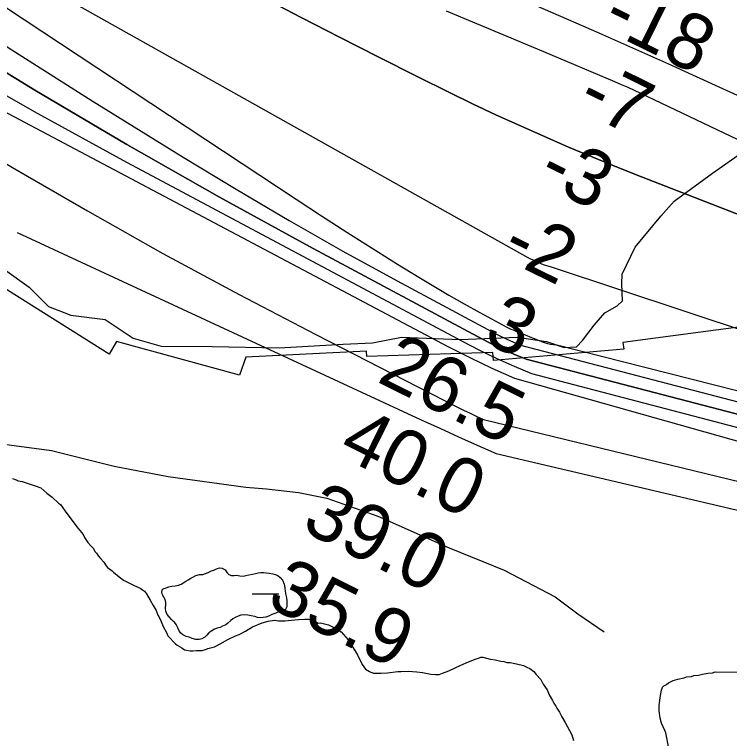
# Model space of a CAD drawing. Extents: x 3263578 to 3301413, y 764927 to 798602.
# Drawn here: x 3281091 to 3281950, y 782337 to 783206 of the extents above; entities that cross this region are included whole.
import ezdxf

# ---------------------------------------------------------------- set-up
doc = ezdxf.new("R2010")
doc.units = 0
for name, color, linetype in [('V-RIVR-EDGE', 7, 'Continuous'), ('V-RIVR-RANG', 7, 'Continuous'), ('V-ROAD-CNTR', 7, 'Continuous'), ('V-RRAP-RVMT', 7, 'Continuous'), ('V-SITE-VEGE', 7, 'Continuous'), ('V-TOPO-DPTH', 7, 'Continuous'), ('V-TOPO-MAJR', 7, 'Continuous'), ('V-TOPO-MINR', 7, 'Continuous'), ('V-TOPO-WATR', 7, 'Continuous'), ('V-WETL-SWMP', 7, 'Continuous')]:
    doc.layers.add(name, color=color, linetype=linetype)

msp = doc.modelspace()

# ---------------------------------------------------------------- linework, layer by layer
at = {"layer": 'V-RIVR-EDGE'}
msp.add_lwpolyline([(3281079.06, 782899.95), (3281109, 782879.01), (3281131.98, 782855.91), (3281158.9, 782845.42), (3281200.18, 782840.1), (3281233.6, 782817.85), (3281267.48, 782808.2), (3281328.77, 782807.61), (3281409.18, 782806.11), (3281485.7, 782810.7), (3281520.91, 782811.92), (3281556.13, 782818.79), (3281626.55, 782816.01), (3281694.8, 782818.88), (3281729.99, 782813.58), (3281751.28, 782806.57), (3281766.06, 782807.4), (3281773.46, 782814.77), (3281787.42, 782833.43), (3281800.06, 782848.18), (3281814.86, 782856.4), (3281821.4, 782862.47), (3281820.58, 782882.9), (3281821.04, 782894.64), (3281836.33, 782926.76), (3281867.29, 782964.07), (3281883.42, 782982.29), (3281929.58, 783015.64), (3281968.33, 783042.93)], dxfattribs=at)
at = {"layer": 'V-ROAD-CNTR'}
msp.add_lwpolyline([(3281078.63, 782690.69), (3281135.53, 782682.77), (3281210.98, 782663.94), (3281275.74, 782651.68), (3281369.17, 782638.83), (3281393.93, 782636.94), (3281432.33, 782632.66), (3281466.46, 782625.58), (3281527.71, 782604.09), (3281613, 782566.06), (3281679.07, 782539.44), (3281740.33, 782507.16), (3281767.85, 782486.68), (3281799.25, 782465.3)], dxfattribs=at)
at = {"layer": 'V-RRAP-RVMT'}
for points in [[(3281665.46, 782800.61), (3281514.13, 782795.79), (3281513.96, 782802.27), (3281368.97, 782794.99), (3281361.31, 782773.49), (3281213.67, 782813.79), (3281204.98, 782798.56), (3281071.75, 782882.28), (3281075.21, 782886.74), (3280952.92, 782963.69), (3280949.52, 782959.02), (3280830.38, 783051.85), (3280817.92, 783039.11), (3280717.22, 783151.35), (3280705.68, 783144.47), (3280621.14, 783274.26)], [(3281972.58, 782832.43), (3281821.58, 782812.34), (3281822.75, 782804.38), (3281666.34, 782791.05), (3281665.46, 782800.61)]]:
    msp.add_lwpolyline(points, dxfattribs=at)
at = {"layer": 'V-SITE-VEGE'}
for points in [[(3281088.65, 782649.38), (3281093.33, 782647.54), (3281095.67, 782646.33), (3281100.37, 782645.67), (3281117.36, 782640.12), (3281122.64, 782638.27), (3281130.19, 782631.68), (3281136.6, 782626.88), (3281144.15, 782619.7)], [(3281144.15, 782619.7), (3281146.48, 782617.9), (3281152.25, 782610.16), (3281156.28, 782604.21), (3281167.84, 782589.32), (3281173.62, 782582.17), (3281175.34, 782578.61), (3281179.37, 782572.66), (3281182.84, 782568.49), (3281185.74, 782565.5), (3281188.04, 782561.34), (3281189.77, 782559.55), (3281192.08, 782555.98), (3281194.98, 782553), (3281198.45, 782548.82), (3281201.33, 782544.66), (3281203.06, 782542.28), (3281208.31, 782538.67), (3281210.05, 782536.88), (3281217.04, 782531.47), (3281222.27, 782527.27), (3281233.96, 782521.21), (3281238.64, 782519.38), (3281242.15, 782517.56), (3281245.07, 782515.75), (3281247.4, 782513.95), (3281249.71, 782510.97), (3281254.3, 782503.24), (3281257.74, 782496.72), (3281261.18, 782490.78), (3281263.46, 782485.45), (3281264.61, 782483.66), (3281267.47, 782477.73), (3281269.73, 782471.81), (3281274.32, 782463.5), (3281275.46, 782460.54), (3281284.74, 782450.98), (3281286.48, 782449.19), (3281292.32, 782446.16), (3281295.23, 782443.76), (3281297.58, 782443.13), (3281302.27, 782442.47), (3281305.22, 782442.43), (3281309.94, 782442.95), (3281316.41, 782442.85), (3281320.55, 782443.97), (3281323.51, 782445.1)], [(3281323.51, 782445.1), (3281331.2, 782447.34), (3281338.32, 782450.77), (3281347.23, 782455.94), (3281356.72, 782460.51), (3281360.86, 782462.21), (3281368.58, 782466.22), (3281376.9, 782471.4), (3281388.74, 782475.94), (3281395.84, 782478.18), (3281403.51, 782479.25), (3281408.21, 782478.59), (3281415.87, 782478.47), (3281420, 782479.01), (3281427.66, 782479.48), (3281432.38, 782480), (3281440.04, 782480.47), (3281444.74, 782480.4), (3281450.03, 782479.15), (3281455.86, 782475.53), (3281458.81, 782476.07), (3281468.2, 782473.58), (3281476.97, 782469.33), (3281483.38, 782465.11), (3281492.08, 782455.56), (3281497.82, 782446.06), (3281503, 782437.73), (3281508.71, 782425.87), (3281512.75, 782420.51), (3281517.42, 782417.5), (3281522.1, 782415.66), (3281531.52, 782415.52), (3281539.19, 782416), (3281551.57, 782417.58), (3281555.7, 782417.52), (3281563.95, 782417.99), (3281574.53, 782417.24), (3281581, 782416.56), (3281590.98, 782414.64), (3281596.86, 782413.97), (3281600.98, 782413.91), (3281605.13, 782415.61), (3281612.83, 782418.44), (3281627.06, 782425.3), (3281636.54, 782429.28), (3281645.42, 782432.68), (3281648.38, 782433.81), (3281651.34, 782434.95), (3281653.7, 782434.91), (3281662.5, 782432.43), (3281668.37, 782431.75), (3281675.41, 782429.88), (3281678.94, 782429.83), (3281682.46, 782428.6), (3281686.58, 782428.54), (3281694.21, 782426.66), (3281702.42, 782424.77), (3281706.52, 782422.94), (3281710.02, 782421.12), (3281714.68, 782417.52), (3281717.57, 782413.95), (3281723.37, 782407.97), (3281726.24, 782402.63), (3281730.84, 782395.5), (3281733.11, 782389.58), (3281737.14, 782383.04), (3281738.85, 782379.48), (3281741.15, 782375.91), (3281742.29, 782373.54), (3281745.75, 782368.78), (3281748.62, 782363.44), (3281752.64, 782356.31), (3281760.66, 782341.47), (3281762.33, 782334.97)], [(3281877.02, 782325.61), (3281873.17, 782343.93), (3281872.03, 782346.89), (3281868.04, 782355.78), (3281866.36, 782361.69), (3281865.31, 782370.54), (3281865.4, 782376.43), (3281866.73, 782386.42), (3281868.04, 782395.23), (3281869.27, 782398.75), (3281871.06, 782400.49), (3281874.03, 782402.21), (3281876.41, 782403.94), (3281882.34, 782406.8), (3281887.67, 782408.48), (3281895.35, 782410.14), (3281898.31, 782411.27), (3281904.2, 782411.77), (3281907.16, 782412.91), (3281912.47, 782413.42), (3281917.2, 782414.52), (3281923.69, 782415.6), (3281929.59, 782416.11), (3281932.55, 782417.24), (3281959.04, 782416.85)]]:
    msp.add_lwpolyline(points, dxfattribs=at)
at = {"layer": 'V-TOPO-DPTH'}
for points in [[(3280689.61, 783473.12), (3281429.64, 782984.43), (3281459.85, 782964.67), (3281490.16, 782945.09), (3281520.65, 782925.78), (3281551.24, 782906.64), (3281576.56, 782890.95), (3281594.68, 782879.96), (3281612.93, 782869.19), (3281631.38, 782858.76), (3281649.96, 782848.57), (3281682.58, 782831.05), (3281684.97, 782829.82), (3281687.38, 782828.65), (3281689.83, 782827.55), (3281692.31, 782826.51), (3281724.05, 782813.8), (3281727.59, 782812.54), (3281731.17, 782811.47), (3281734.83, 782810.68), (3281738.53, 782810.07), (3281742.28, 782809.73), (3282707.96, 782564.89)], [(3280689.61, 783473.12), (3281429.64, 782984.43), (3281459.85, 782964.67), (3281490.16, 782945.09), (3281520.65, 782925.78), (3281551.24, 782906.64), (3281576.56, 782890.95), (3281594.68, 782879.96), (3281612.93, 782869.19), (3281631.38, 782858.76), (3281649.96, 782848.57), (3281682.58, 782831.05), (3281684.97, 782829.82), (3281687.38, 782828.65), (3281689.83, 782827.55), (3281692.31, 782826.51), (3281724.05, 782813.8), (3281727.59, 782812.54), (3281731.17, 782811.47), (3281734.83, 782810.68), (3281738.53, 782810.07), (3281742.28, 782809.73), (3282707.96, 782564.89)], [(3283888.62, 781898.87), (3282781.99, 782505.42), (3282768.2, 782511.2), (3282754.31, 782516.74), (3282740.29, 782521.93), (3282726.18, 782526.88), (3281705.55, 782792.33), (3281690.7, 782798.57), (3281676, 782805.13), (3281661.52, 782812.19), (3281647.2, 782819.56), (3281449.73, 782925.45), (3281337.42, 782987.11), (3281225.94, 783050.21), (3281115.73, 783115.49), (3281006.36, 783182.23), (3280644.33, 783408.02)], [(3281374.9, 783366.24), (3281790.18, 783185.21), (3281819.02, 783172.56), (3281847.81, 783159.8), (3281876.55, 783146.91), (3281905.24, 783133.92), (3282089.17, 783050.1), (3282209.69, 782994.9), (3282330.06, 782939.39), (3282450.21, 782883.41), (3282570.23, 782827.12), (3282802.68, 782717.54), (3282816.78, 782710.34), (3282830.55, 782702.59), (3282843.81, 782694), (3283239.54, 782446.67), (3283284.2, 782420.65), (3283328.95, 782394.78), (3283373.82, 782369.14)], [(3281374.9, 783366.24), (3281790.18, 783185.21), (3281819.02, 783172.56), (3281847.81, 783159.8), (3281876.55, 783146.91), (3281905.24, 783133.92), (3282089.17, 783050.1), (3282209.69, 782994.9), (3282330.06, 782939.39), (3282450.21, 782883.41), (3282570.23, 782827.12), (3282802.68, 782717.54), (3282816.78, 782710.34), (3282830.55, 782702.59), (3282843.81, 782694), (3283239.54, 782446.67), (3283284.2, 782420.65), (3283328.95, 782394.78), (3283373.82, 782369.14)], [(3282133.57, 782898.94), (3281844.3, 783011.42), (3281814.93, 783023.04), (3281785.66, 783034.9), (3281756.53, 783047.12), (3281727.51, 783059.57), (3281698.65, 783072.41), (3281669.92, 783085.53), (3281641.38, 783099.06), (3281612.97, 783112.86), (3281575.67, 783131.33), (3281528.81, 783154.78), (3281482.1, 783178.51), (3281435.6, 783202.66), (3281389.24, 783227.08)], [(3282133.57, 782898.94), (3281844.3, 783011.42), (3281814.93, 783023.04), (3281785.66, 783034.9), (3281756.53, 783047.12), (3281727.51, 783059.57), (3281698.65, 783072.41), (3281669.92, 783085.53), (3281641.38, 783099.06), (3281612.97, 783112.86), (3281575.67, 783131.33), (3281528.81, 783154.78), (3281482.1, 783178.51), (3281435.6, 783202.66), (3281389.24, 783227.08)]]:
    msp.add_lwpolyline(points, dxfattribs=at)
at = {"layer": 'V-TOPO-MAJR'}
msp.add_lwpolyline([(3280584.22, 783321.59), (3281088.95, 783022.68), (3281178.89, 782970.54), (3281269.44, 782919.52), (3281360.93, 782870.19), (3281453.04, 782821.99), (3281622.25, 782735.43), (3281630.26, 782731.43), (3281638.31, 782727.53), (3281646.43, 782723.77), (3281654.59, 782720.12), (3282470.29, 782522.13), (3282484.68, 782519.33), (3282498.93, 782515.58), (3282678.05, 782459.07), (3282702.24, 782450.76), (3282726.09, 782441.65), (3282749.45, 782431.33), (3282772.48, 782420.22), (3282910.36, 782349.3), (3283832.02, 781841.15)], dxfattribs=at)
at = {"layer": 'V-TOPO-MINR'}
for points in [[(3280700.93, 783489.39), (3280735.51, 783467.15), (3280781.98, 783437.85), (3280828.79, 783409.13), (3280876.11, 783381.26), (3280923.78, 783353.96), (3281707.72, 782914.46), (3281716.77, 782909.99), (3281726.05, 782906.18), (3281735.68, 782903.36), (3282698.87, 782583.95), (3282734.08, 782571.37), (3282769.08, 782558.25), (3282803.77, 782544.31), (3282838.24, 782529.84), (3283666.78, 782075.76)], [(3280672.4, 783448.38), (3280804.01, 783355.07), (3280897.78, 783289.89), (3280992.34, 783225.89), (3281088.08, 783163.66), (3281184.6, 783102.62), (3281293.78, 783034.97), (3281357.21, 782996.49), (3281421.1, 782958.8), (3281485.67, 782922.31), (3281550.71, 782886.61), (3281664.89, 782825.31), (3281673.25, 782821.01), (3281681.69, 782816.89), (3281690.27, 782813.06), (3281698.93, 782809.42), (3282738.21, 782538.39), (3282759.23, 782530.57), (3282780.05, 782522.23), (3282800.74, 782513.56), (3283832.87, 781945.93)], [(3280644.33, 783408.02), (3281006.36, 783182.23), (3281115.73, 783115.49), (3281225.94, 783050.21), (3281337.42, 782987.11), (3281449.73, 782925.45), (3281647.2, 782819.56), (3281661.52, 782812.19), (3281676, 782805.13), (3281690.7, 782798.57), (3281705.55, 782792.33), (3282726.18, 782526.88), (3282740.29, 782521.93), (3282754.31, 782516.74), (3282768.2, 782511.2), (3282781.99, 782505.42), (3283888.62, 781898.87)], [(3281374.9, 783366.24), (3281790.18, 783185.21), (3281819.02, 783172.56), (3281847.81, 783159.8), (3281876.55, 783146.91), (3281905.24, 783133.92), (3282089.17, 783050.1), (3282209.69, 782994.9), (3282330.06, 782939.39), (3282450.21, 782883.41), (3282570.23, 782827.12), (3282802.68, 782717.54), (3282816.78, 782710.34), (3282830.55, 782702.59), (3282843.81, 782694), (3283239.54, 782446.67), (3283284.2, 782420.65), (3283328.95, 782394.78), (3283373.82, 782369.14)], [(3280610.01, 783358.68), (3280657.9, 783326.63), (3280707.99, 783294.22), (3280758.7, 783262.86), (3280810.37, 783233.08), (3280862.66, 783204.35), (3281611.66, 782807.79), (3281637.98, 782794.39), (3281664.57, 782781.55), (3281691.55, 782769.56), (3282392.85, 782572.25), (3282414.34, 782567.91), (3282744.49, 782489.14), (3283892.65, 781840.02)], [(3281389.24, 783227.08), (3281435.6, 783202.66), (3281482.1, 783178.51), (3281528.81, 783154.78), (3281575.67, 783131.33), (3281612.97, 783112.86), (3281641.38, 783099.06), (3281669.92, 783085.53), (3281698.65, 783072.41), (3281727.51, 783059.57), (3281756.53, 783047.12), (3281785.66, 783034.9), (3281814.93, 783023.04), (3281844.3, 783011.42), (3282133.57, 782898.94)], [(3280896.68, 783218.07), (3281004.93, 783152.58), (3281114.79, 783089.83), (3281225.71, 783028.91), (3281629.45, 782813.71), (3281649.77, 782803.31), (3281670.29, 782793.35), (3281691.13, 782784.07), (3281712.17, 782775.24), (3282742.38, 782505.51), (3282749.4, 782502.93), (3282756.34, 782500.17), (3282763.24, 782497.28), (3282817.84, 782473.6), (3282827.05, 782469.42), (3282836.17, 782465.05), (3282845.15, 782460.39), (3282854.03, 782455.53), (3282862.8, 782450.47), (3282871.52, 782445.32), (3282880.17, 782440.06), (3282888.77, 782434.72), (3283887.68, 781870.42)], [(3281609.48, 783210.45), (3281645.9, 783195.33), (3281682.29, 783180.16), (3281718.65, 783164.91), (3281754.99, 783149.61), (3281811.83, 783125.6), (3281819.71, 783122.22), (3281827.55, 783118.77), (3281835.35, 783115.21), (3281843.12, 783111.59), (3282034.83, 783020.69)], [(3281094.23, 782944.37), (3281579.47, 782719.8), (3281601.91, 782709.51), (3281624.39, 782699.34), (3281646.95, 782689.34), (3281669.56, 782679.44), (3282561.41, 782470.16), (3282569.54, 782469.49), (3282577.56, 782467.99), (3282585.5, 782465.93), (3282690.72, 782432.73), (3282704.83, 782427.88), (3282718.74, 782422.57), (3282732.37, 782416.55), (3282745.8, 782410.07), (3282827.03, 782368.29), (3282832.59, 782365.13), (3283843.91, 781816.95)]]:
    msp.add_lwpolyline(points, dxfattribs=at)
at = {"layer": 'V-TOPO-WATR'}
msp.add_lwpolyline([(3280689.61, 783473.12), (3281429.64, 782984.43), (3281459.85, 782964.67), (3281490.16, 782945.09), (3281520.65, 782925.78), (3281551.24, 782906.64), (3281576.56, 782890.95), (3281594.68, 782879.96), (3281612.93, 782869.19), (3281631.38, 782858.76), (3281649.96, 782848.57), (3281682.58, 782831.05), (3281684.97, 782829.82), (3281687.38, 782828.65), (3281689.83, 782827.55), (3281692.31, 782826.51), (3281724.05, 782813.8), (3281727.59, 782812.54), (3281731.17, 782811.47), (3281734.83, 782810.68), (3281738.53, 782810.07), (3281742.28, 782809.73), (3282707.96, 782564.89)], dxfattribs=at)
at = {"layer": 'V-WETL-SWMP'}
msp.add_line((3281376.71, 782510.99), (3281408.71, 782510.99), dxfattribs=at)
for points in [[(3281268.85, 782516.5), (3281276.65, 782519.42), (3281280.2, 782520.21), (3281284.26, 782520.66), (3281288.32, 782521.28), (3281291.37, 782522.41), (3281294.44, 782524.56), (3281296.99, 782526.21), (3281299.71, 782527.69), (3281302.78, 782529.66), (3281305.5, 782530.97), (3281308.9, 782532.78), (3281313.3, 782533.89), (3281317.18, 782534.17), (3281320.4, 782535.14), (3281323.62, 782536.44), (3281327.7, 782538.4), (3281330.75, 782539.37), (3281333.64, 782541.01), (3281337.37, 782541.97), (3281340.4, 782541.76), (3281344.08, 782539.51), (3281346.39, 782536.1), (3281348.72, 782534.21), (3281351.74, 782532.99), (3281354.95, 782532.94), (3281357.99, 782533.23), (3281361.69, 782532.67), (3281365.73, 782532.27), (3281369.12, 782532.9), (3281372.5, 782533.69), (3281376.9, 782534.47), (3281380.45, 782535.43), (3281383.67, 782536.22), (3281386.88, 782536.35), (3281390.59, 782536.29), (3281393.62, 782536.08), (3281397.15, 782535.52), (3281401.36, 782534.78), (3281404.39, 782534.06), (3281407.57, 782532.83), (3281410.4, 782530.43), (3281413.06, 782527.36), (3281415.01, 782522.6), (3281415.96, 782518.04), (3281416.4, 782513.98), (3281417, 782509.08), (3281417.8, 782506.03), (3281418.25, 782502.32), (3281418.37, 782498.6), (3281418.32, 782495.23), (3281416.75, 782492.22), (3281414.03, 782490.74), (3281411.31, 782489.43), (3281407.93, 782488.81), (3281403.69, 782487.35), (3281400.3, 782486.05), (3281397.24, 782484.41), (3281393, 782482.95), (3281389.79, 782482.33), (3281386.75, 782482.2), (3281383.21, 782482.59), (3281379.68, 782483.49), (3281375.48, 782484.39), (3281371.45, 782485.3), (3281367.4, 782485.53), (3281363.18, 782485.08), (3281359.96, 782484.12), (3281356.22, 782482.49), (3281353.33, 782480.67), (3281350.94, 782478.69), (3281347.35, 782475.7), (3281344.96, 782473.71), (3281341.06, 782471.92), (3281338.17, 782470.61), (3281334.78, 782469.48), (3281331.56, 782468.35), (3281327.99, 782466.54), (3281324.57, 782463.9), (3281322.35, 782461.4), (3281319.94, 782458.73), (3281316.2, 782456.77), (3281312.82, 782455.97), (3281309.11, 782456.2), (3281304.57, 782457.28), (3281301.05, 782458.68), (3281297.36, 782459.74), (3281293.17, 782461.83), (3281290.67, 782463.89), (3281288.69, 782467.12), (3281287.22, 782470.18), (3281285.26, 782474.26), (3281283.27, 782476.82), (3281282.1, 782477.68), (3281281.27, 782478.54), (3281279.61, 782479.91), (3281276.79, 782483.16), (3281274.47, 782486.06), (3281273.01, 782490.13), (3281272.38, 782493.17), (3281272.42, 782495.54)], [(3281272.42, 782495.54), (3281272.78, 782497.05), (3281272.83, 782500.59), (3281272.2, 782503.97), (3281270.73, 782506.69), (3281268.92, 782509.76), (3281267.95, 782512.81), (3281268.85, 782516.5)]]:
    msp.add_lwpolyline(points, dxfattribs=at)

# ---------------------------------------------------------------- texts
at = {"layer": 'V-RIVR-RANG'}
for s, rotation, p in [('-18', 333.80794, (3281794.12, 783190.4)), ('-7', 333.80794, (3281764.07, 783093.74)), ('-3', 333.80794, (3281716.98, 783005.46)), ('-2', 333.80794, (3281673.2, 782915.55)), ('3', 333.80794, (3281652.14, 782814.47)), ('26.5', 333.59833, (3281524.9, 782766.1)), ('40.0', 333.59833, (3281478.04, 782677.72)), ('39.0', 333.59833, (3281433.79, 782588.04)), ('35.9', 333.59833, (3281391.9, 782497.19))]:
    msp.add_text(s, height=67, rotation=rotation, dxfattribs=at).set_placement(p)

doc.saveas('drawing.dxf')
